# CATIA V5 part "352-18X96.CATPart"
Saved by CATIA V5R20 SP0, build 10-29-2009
Part number: 352-18X96
Definition: NONE
Nomenclature: 352-18X96
Source: Unknown
Description: 352-18X96
Bounding box of the stored display mesh (mm): x 0 to 96, y -13 to 13, z -13 to 13
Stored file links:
  C:\Users\Utente\Desktop\IO LAVORO\3D X SITO CF\X SITO\PLASTICA\352\352-18X96.CATPart
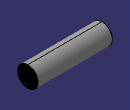
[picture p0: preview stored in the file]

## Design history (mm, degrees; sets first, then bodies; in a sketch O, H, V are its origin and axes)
Body1 "352-18X96" (main body)
  Solid1: solid without history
